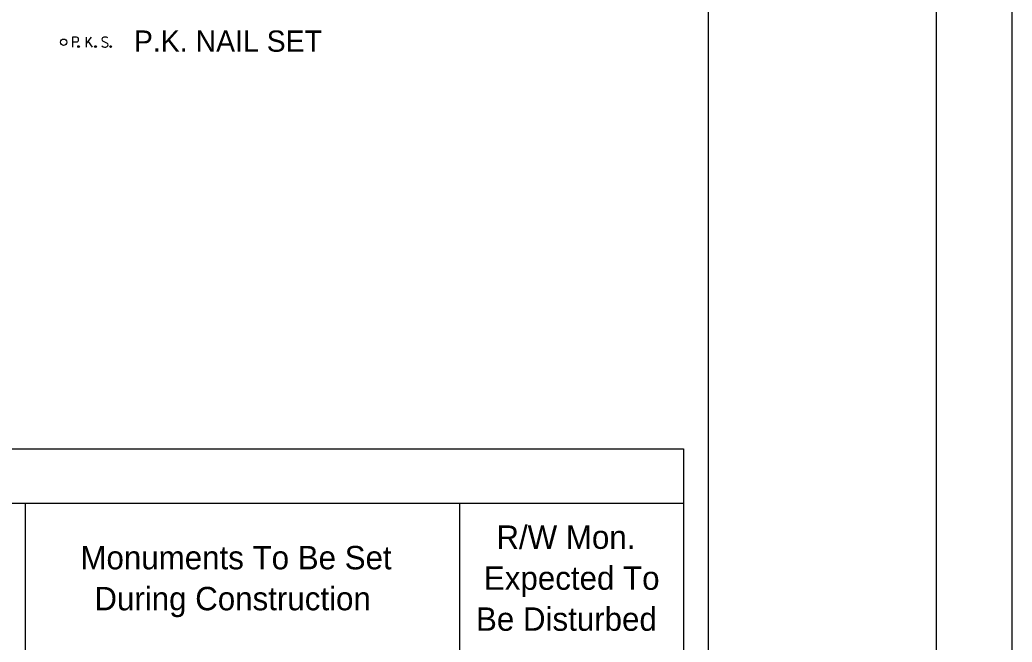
# Model space of a CAD drawing. Extents: x 0 to 34, y 0 to 22.
# Drawn here: x 27.47 to 34, y 6.36 to 10.45 of the extents above; entities that cross this region are included whole.
import ezdxf

# ---------------------------------------------------------------- set-up
doc = ezdxf.new("R2010")
doc.units = 0
for name, color, linetype in [('_CIVIL_CONSTRUCTION', 7, 'Continuous'), ('GE_X_Alignment_100_Bearings', 7, 'Continuous'), ('SG_X_Poles', 7, 'Continuous'), ('SH_Masking', 7, 'Continuous')]:
    doc.layers.add(name, color=color, linetype=linetype)

msp = doc.modelspace()

# ---------------------------------------------------------------- linework, layer by layer
at = {"layer": '_CIVIL_CONSTRUCTION'}
msp.add_line((32, 0.5), (32, 21.5), dxfattribs=at)
msp.add_lwpolyline([(1.5, 21.5), (33.5, 21.5), (33.5, 0.5), (1.5, 0.5)], close=True, dxfattribs=at)
at = {"layer": 'GE_X_Alignment_100_Bearings'}
for p, q in [((27.907, 10.2705), (27.907, 10.3371)), ((27.907, 10.2946), (27.939, 10.3371)), ((27.8143, 10.3052), (27.841, 10.3052)), ((27.9173, 10.3084), (27.9448, 10.2705)), ((28.0128, 10.3138), (28.0433, 10.298))]:
    msp.add_line(p, q, dxfattribs=at)
msp.add_lwpolyline([(27.841, 10.3371), (27.8143, 10.3371), (27.8143, 10.2705)], dxfattribs=at)
for centre, radius in [((27.7558, 10.3038), 0.0206), ((27.8544, 10.275), 0.00583), ((27.9655, 10.275), 0.00583), ((28.0655, 10.275), 0.00583)]:
    msp.add_circle(centre, radius, dxfattribs=at)
for centre, radius, start, end in [((27.8385, 10.3212), 0.0162, 278.88026, 81.11974), ((28.0193, 10.3237), 0.0118, 126.25873, 236.36755), ((28.0291, 10.3025), 0.0349, 61.34633, 118.65367), ((28.0276, 10.2987), 0.0276, 223.66947, 304.39628), ((28.0334, 10.287), 0.0148, 311.48833, 47.93584)]:
    msp.add_arc(centre, radius, start, end, dxfattribs=at)
at = {"layer": 'SG_X_Poles'}
for p, q in [((17.5404, 7.627), (30.3612, 7.627)), ((30.3612, 7.627), (31.8369, 7.627)), ((31.8369, 7.627), (31.8369, 4.3592)), ((17.5404, 7.2712), (30.3612, 7.2712)), ((27.5019, 7.2712), (27.5019, 5.6241)), ((30.3612, 7.2712), (31.8369, 7.2712)), ((30.3612, 7.2712), (30.3612, 5.6241))]:
    msp.add_line(p, q, dxfattribs=at)
at = {"layer": 'SH_Masking'}
msp.add_lwpolyline([(0, 0), (34, 0), (34, 22), (0, 22)], close=True, dxfattribs=at)

# ---------------------------------------------------------------- texts
at = {"layer": 'GE_X_Alignment_100_Bearings'}
msp.add_text('P.K. NAIL SET', height=0.14, dxfattribs=at).set_placement((28.2186, 10.2409))
at = {"layer": 'SG_X_Poles'}
for s, p in [('R/W Mon.', (30.6046, 6.9696)), ('Monuments To Be Set', (27.8664, 6.8348)), ('Expected To', (30.5227, 6.7001)), ('During Construction', (27.9582, 6.5653)), ('Be Disturbed', (30.4705, 6.4306))]:
    msp.add_text(s, height=0.154, dxfattribs=at).set_placement(p)

doc.saveas('drawing.dxf')
